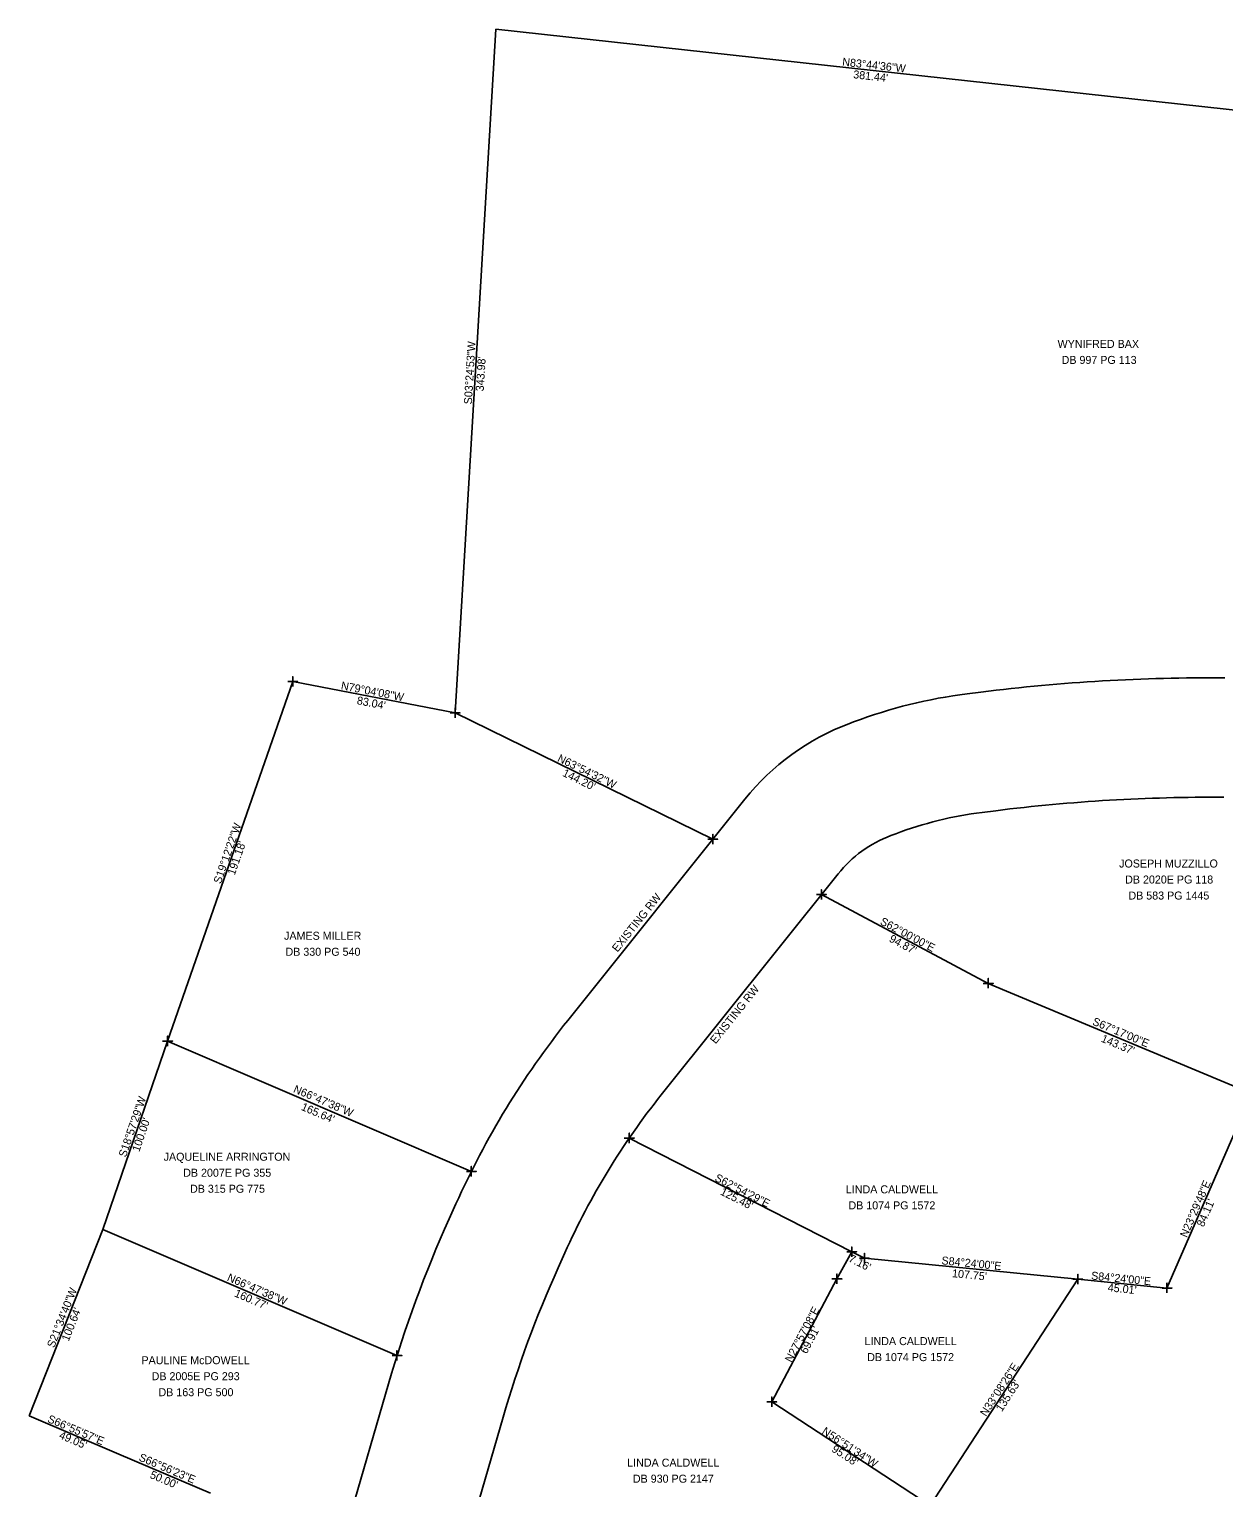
# Model space of a CAD drawing. Extents: x 783966 to 785075, y 667781 to 668938.
# Drawn here: x 784055 to 784655, y 668205 to 668938 of the extents above; entities that cross this region are included whole.
import ezdxf

# ---------------------------------------------------------------- set-up
doc = ezdxf.new("R2010")
doc.units = 0
for name, color, linetype in [('Exist Property Corner CELL', 7, 'Continuous'), ('Exist Property Line', 7, 'Continuous'), ('Exist Property Text', 7, 'Continuous'), ('Exist Right of Way Line', 7, 'Continuous'), ('Exist Right of Way Text', 7, 'Continuous')]:
    doc.layers.add(name, color=color, linetype=linetype)

msp = doc.modelspace()

# ---------------------------------------------------------------- linework, layer by layer
at = {"layer": 'Exist Property Corner CELL'}
for p, q in [((784187.54, 668609.88), (784187.54, 668609.88)), ((784269.07, 668594.14), (784269.07, 668594.14)), ((784398.58, 668530.72), (784398.58, 668530.72)), ((784453.15, 668502.88), (784453.15, 668502.88)), ((784536.91, 668458.34), (784536.91, 668458.34)), ((784124.65, 668429.35), (784124.65, 668429.35)), ((784356.6, 668380.66), (784356.6, 668380.66)), ((784277.26, 668363.92), (784277.26, 668363.92)), ((784468.32, 668323.52), (784468.32, 668323.52)), ((784474.69, 668320.26), (784474.69, 668320.26)), ((784460.93, 668309.91), (784460.93, 668309.91)), ((784581.93, 668309.74), (784581.93, 668309.74)), ((784626.72, 668305.35), (784626.72, 668305.35)), ((784239.92, 668271.42), (784239.92, 668271.42)), ((784428.17, 668248.15), (784428.17, 668248.15))]:
    msp.add_line(p, q, dxfattribs=at)
for points in [[(784185.04, 668609.88), (784190.04, 668609.88), (784187.54, 668609.88), (784187.54, 668612.38), (784187.54, 668607.38)], [(784266.57, 668594.14), (784271.57, 668594.14), (784269.07, 668594.14), (784269.07, 668596.64), (784269.07, 668591.64)], [(784396.08, 668530.72), (784401.08, 668530.72), (784398.58, 668530.72), (784398.58, 668533.22), (784398.58, 668528.22)], [(784450.65, 668502.88), (784455.65, 668502.88), (784453.15, 668502.88), (784453.15, 668505.38), (784453.15, 668500.38)], [(784534.41, 668458.34), (784539.41, 668458.34), (784536.91, 668458.34), (784536.91, 668460.84), (784536.91, 668455.84)], [(784122.15, 668429.35), (784127.15, 668429.35), (784124.65, 668429.35), (784124.65, 668431.85), (784124.65, 668426.85)], [(784354.1, 668380.66), (784359.1, 668380.66), (784356.6, 668380.66), (784356.6, 668383.16), (784356.6, 668378.16)], [(784274.76, 668363.92), (784279.76, 668363.92), (784277.26, 668363.92), (784277.26, 668366.42), (784277.26, 668361.42)], [(784465.82, 668323.52), (784470.82, 668323.52), (784468.32, 668323.52), (784468.32, 668326.02), (784468.32, 668321.02)], [(784472.19, 668320.26), (784477.19, 668320.26), (784474.69, 668320.26), (784474.69, 668322.76), (784474.69, 668317.76)], [(784458.43, 668309.91), (784463.43, 668309.91), (784460.93, 668309.91), (784460.93, 668312.41), (784460.93, 668307.41)], [(784579.43, 668309.74), (784584.43, 668309.74), (784581.93, 668309.74), (784581.93, 668312.24), (784581.93, 668307.24)], [(784624.22, 668305.35), (784629.22, 668305.35), (784626.72, 668305.35), (784626.72, 668307.85), (784626.72, 668302.85)], [(784237.42, 668271.42), (784242.42, 668271.42), (784239.92, 668271.42), (784239.92, 668273.92), (784239.92, 668268.92)], [(784425.67, 668248.15), (784430.67, 668248.15), (784428.17, 668248.15), (784428.17, 668250.65), (784428.17, 668245.66)]]:
    msp.add_lwpolyline(points, dxfattribs=at)
at = {"layer": 'Exist Property Line'}
for p, q in [((784289.56, 668937.51), (784269.07, 668594.14)), ((784668.73, 668895.94), (784289.56, 668937.51)), ((784187.54, 668609.88), (784124.65, 668429.35)), ((784269.07, 668594.14), (784187.54, 668609.88)), ((784398.58, 668530.72), (784269.07, 668594.14)), ((784453.15, 668502.88), (784536.91, 668458.34)), ((784536.91, 668458.34), (784669.16, 668402.97)), ((784124.65, 668429.35), (784092.16, 668334.77)), ((784276.89, 668364.08), (784124.65, 668429.35)), ((784356.6, 668380.66), (784468.32, 668323.52)), ((784626.72, 668305.35), (784660.25, 668382.49)), ((784277.26, 668363.92), (784276.89, 668364.08)), ((784092.16, 668334.77), (784055.14, 668241.18)), ((784239.92, 668271.42), (784092.16, 668334.77)), ((784460.93, 668309.91), (784468.32, 668323.52)), ((784468.32, 668323.52), (784474.69, 668320.26)), ((784474.69, 668320.26), (784581.93, 668309.74)), ((784428.17, 668248.15), (784460.93, 668309.91)), ((784507.78, 668196.18), (784581.93, 668309.74)), ((784581.93, 668309.74), (784626.72, 668305.35)), ((784507.78, 668196.18), (784428.17, 668248.15)), ((784055.14, 668241.18), (784100.27, 668221.96)), ((784100.27, 668221.96), (784146.28, 668202.38))]:
    msp.add_line(p, q, dxfattribs=at)
at = {"layer": 'Exist Right of Way Line'}
for p, q in [((784526.36, 668603.73), (784533.21, 668604.59)), ((784466.91, 668588.73), (784469.31, 668589.63)), ((784325.76, 668439.76), (784414.66, 668550.81)), ((784533.81, 668544.2), (784540.66, 668545.05)), ((784533.81, 668544.2), (784540.66, 668545.05)), ((784488.05, 668532.58), (784490.45, 668533.48)), ((784488.05, 668532.58), (784490.45, 668533.48)), ((784372.62, 668402.3), (784461.5, 668513.3)), ((784372.62, 668402.3), (784461.5, 668513.3)), ((784325.74, 668439.75), (784325.76, 668439.76)), ((784266.11, 668340.01), (784269.53, 668347.62)), ((784320.83, 668315.41), (784324.26, 668323.04)), ((784320.83, 668315.41), (784324.26, 668323.04)), ((784320.83, 668315.4), (784320.83, 668315.41)), ((784320.83, 668315.4), (784320.83, 668315.41)), ((784176.63, 668054.18), (784235.61, 668257.19)), ((784229.63, 668021.56), (784293.23, 668240.45)), ((784234.25, 668037.44), (784293.23, 668240.45))]:
    msp.add_line(p, q, dxfattribs=at)
for centre, radius, start, end in [((784648.69, 667681.79), 930, 89.56667, 97.13333), ((784557.41, 668355.67), 250, 97.13333, 110.63333), ((784509.9, 668474.55), 122, 110.63333, 141.31667), ((784648.69, 667681.79), 870, 89.56667, 97.13333), ((784648.69, 667681.79), 870, 89.56667, 97.13333), ((784557.41, 668355.67), 190, 97.13333, 110.63333), ((784557.41, 668355.67), 190, 97.13333, 110.63333), ((784509.9, 668474.55), 62, 110.63333, 141.31667), ((784509.9, 668474.55), 62, 110.63333, 141.31667), ((784661.79, 668171.47), 430, 141.39843, 155.81667), ((784661.79, 668171.47), 370, 141.40168, 155.81667), ((784661.79, 668171.47), 370, 141.40168, 155.81667), ((784840.59, 668081.43), 630, 155.76658, 163.8), ((784840.59, 668081.43), 570, 155.76534, 163.8), ((784840.59, 668081.43), 570, 155.76534, 163.8)]:
    msp.add_arc(centre, radius, start, end, dxfattribs=at)

# ---------------------------------------------------------------- texts
at = {"layer": 'Exist Property Text'}
for s, rotation, p in [('N83°44\'36"W', 353.74344, (784463.43, 668919.21)), ("381.44'", 353.74344, (784468.95, 668912.9)), ('S03°24\'53"W', 86.58533, (784277.53, 668749.01)), ("343.98'", 86.58533, (784283.48, 668755.57)), ('N79°04\'08"W', 349.06883, (784211.53, 668606.04)), ("83.04'", 349.06883, (784219.52, 668598.6)), ('N63°54\'32"W', 333.90899, (784320.14, 668570.02)), ("144.20'", 333.90899, (784322.67, 668562.66)), ('S19°12\'22"W', 70.79399, (784151.4, 668508.05)), ("191.18'", 70.79399, (784158.39, 668512.37)), ('S62°00\'00"E', 332, (784482.2, 668488.18)), ("94.87'", 332, (784486.77, 668479.54)), ('S67°17\'00"E', 337.28333, (784588.88, 668437.71)), ("143.37'", 337.28333, (784593.26, 668429.17)), ('N66°47\'38"W', 336.79399, (784187.5, 668403.78)), ('S18°57\'29"W', 71.04201, (784103.72, 668370.69)), ("165.64'", 336.79399, (784191.42, 668394.9)), ("100.00'", 71.04201, (784110.46, 668373.47)), ('S62°54\'29"E', 332.90806, (784399.14, 668359.38)), ("125.48'", 332.90806, (784401.96, 668352.47)), ('N23°29\'48"E', 66.50333, (784636.71, 668330.36)), ("84.11'", 66.50333, (784645.12, 668335.69)), ("7.16'", 332.90806, (784466.42, 668318.89)), ('S84°24\'00"E', 354.4, (784513.29, 668317.27)), ('N66°47\'38"W', 336.79399, (784154.24, 668309.17)), ("107.75'", 354.4, (784518.6, 668310.82)), ('S84°24\'00"E', 354.4, (784588.47, 668309.64)), ('S21°34\'40"W', 68.42218, (784067.67, 668275)), ("160.77'", 336.79399, (784157.89, 668301.25)), ("45.01'", 354.4, (784596.83, 668303.7)), ("100.64'", 68.42218, (784074.98, 668278.29)), ('N27°57\'08"E', 62.0478, (784438.07, 668267.64)), ("69.91'", 62.0478, (784445.7, 668271.98)), ('N33°08\'26"E', 56.85944, (784535.83, 668240.51)), ("135.63'", 56.85944, (784543.76, 668242.93)), ('S66°55\'57"E', 336.93239, (784064.01, 668238.13)), ("49.05'", 336.93239, (784069.8, 668230.01)), ('N56°51\'34"W', 326.8594, (784453, 668232.46)), ("95.08'", 326.8594, (784457.89, 668223.55)), ('S66°56\'23"E', 336.93983, (784109.85, 668218.85)), ("50.00'", 336.93983, (784115.45, 668210.11))]:
    msp.add_text(s, height=4.02, rotation=rotation, dxfattribs=at).set_placement(p)
for s, p in [('WYNIFRED BAX', (784571.76, 668777.44)), ('DB 997 PG 113', (784573.79, 668769.4)), ('JOSEPH MUZZILLO', (784602.68, 668516.51)), ('DB 2020E PG 118', (784605.69, 668508.47)), ('DB 583 PG 1445', (784607.34, 668500.43)), ('JAMES MILLER', (784183.18, 668480.23)), ('DB 330 PG 540', (784183.9, 668472.19)), ('JAQUELINE ARRINGTON', (784122.7, 668369.26)), ('DB 2007E PG 355', (784132.52, 668361.22)), ('DB 315 PG 775', (784135.95, 668353.18)), ('LINDA CALDWELL', (784465.4, 668352.88)), ('DB 1074 PG 1572', (784466.7, 668344.84)), ('LINDA CALDWELL', (784474.81, 668276.67)), ('PAULINE McDOWELL', (784111.55, 668267.09)), ('DB 1074 PG 1572', (784476.11, 668268.63)), ('DB 2005E PG 293', (784116.67, 668259.05)), ('DB 163 PG 500', (784120.11, 668251.01)), ('LINDA CALDWELL', (784355.57, 668215.63)), ('DB 930 PG 2147', (784358.41, 668207.59))]:
    msp.add_text(s, height=4.02, dxfattribs=at).set_placement(p)
at = {"layer": 'Exist Right of Way Text'}
for p in [(784350.68, 668473.74), (784399.98, 668427.64)]:
    msp.add_text('EXISTING RW', height=4.02, rotation=51.31667, dxfattribs=at).set_placement(p)

doc.saveas('drawing.dxf')
